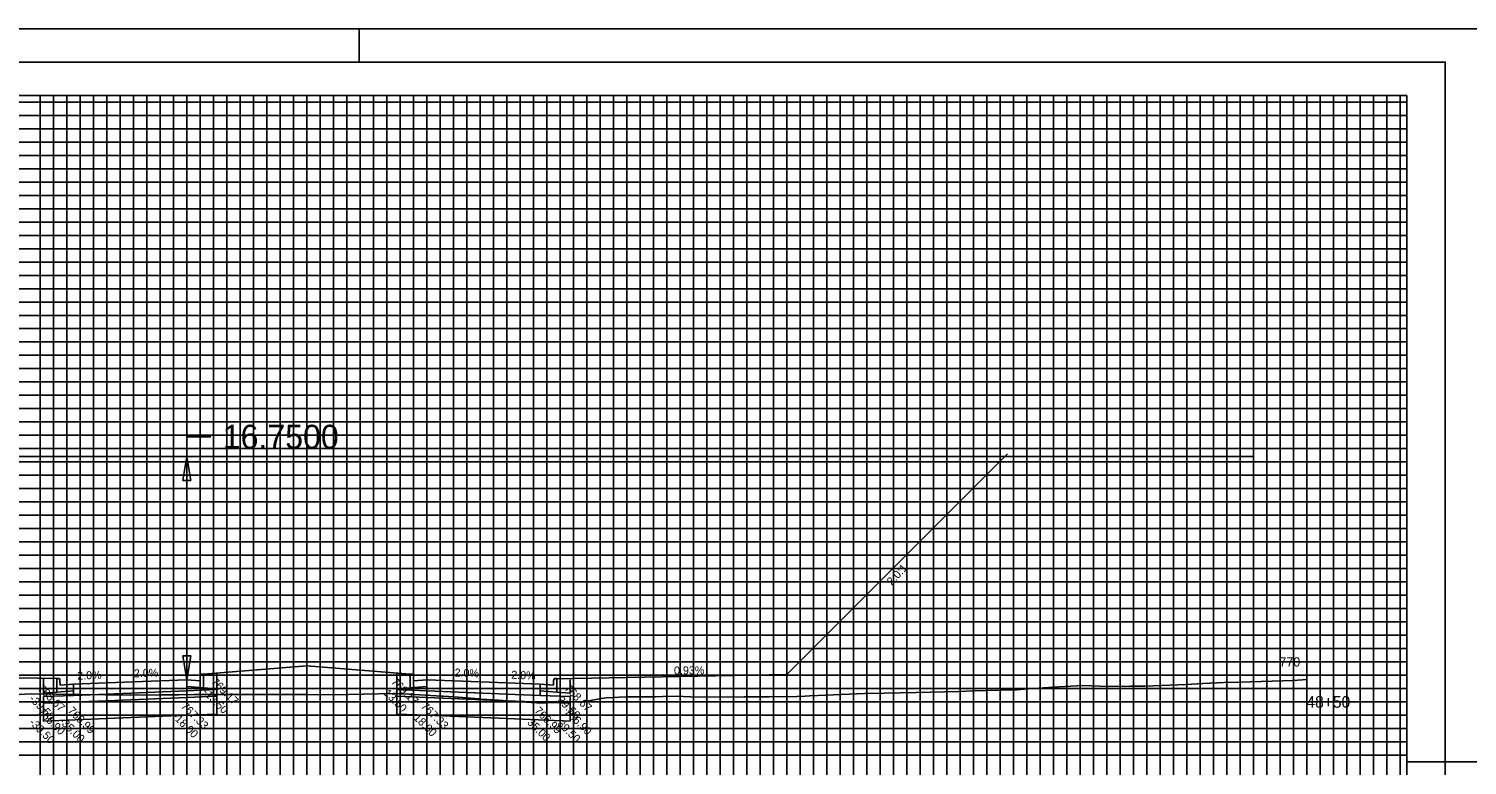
# Model space of a CAD drawing. Extents: x 578243 to 601557, y 174899 to 175559.
# Drawn here: x 600318.2 to 600533.9, y 175448.3 to 175558.8 of the extents above; entities that cross this region are included whole.
import ezdxf

# ---------------------------------------------------------------- set-up
doc = ezdxf.new("R2010")
doc.units = 0
for name, color, linetype in [('E_PROF_Grid', 7, 'Continuous'), ('E_PROF_GridMin', 7, 'Continuous'), ('P_CRDR_Label', 7, 'Continuous'), ('P_CRDR_Link', 7, 'Continuous'), ('P_E_XS_Ground', 7, 'Continuous'), ('P_RW_SlopeIntercepts', 7, 'Continuous'), ('P_XS_Text', 7, 'Continuous'), ('PLT_Sheet_Border', 7, 'Continuous'), ('PLT_Sheet_Info', 7, 'Continuous')]:
    doc.layers.add(name, color=color, linetype=linetype)

msp = doc.modelspace()

# ---------------------------------------------------------------- linework, layer by layer
at = {"layer": 'E_PROF_Grid'}
for p, q in [((600319.84, 175353.8), (600319.84, 175548.8)), ((600329.84, 175353.8), (600329.84, 175548.8)), ((600339.84, 175353.8), (600339.84, 175548.8)), ((600349.84, 175353.8), (600349.84, 175548.8)), ((600359.84, 175353.8), (600359.84, 175548.8)), ((600369.84, 175353.8), (600369.84, 175548.8)), ((600379.84, 175353.8), (600379.84, 175548.8)), ((600389.84, 175353.8), (600389.84, 175548.8)), ((600399.84, 175353.8), (600399.84, 175548.8)), ((600409.84, 175353.8), (600409.84, 175548.8)), ((600419.84, 175353.8), (600419.84, 175548.8)), ((600429.84, 175353.8), (600429.84, 175548.8)), ((600439.84, 175353.8), (600439.84, 175548.8)), ((600449.84, 175353.8), (600449.84, 175548.8)), ((600459.84, 175353.8), (600459.84, 175548.8)), ((600469.84, 175353.8), (600469.84, 175548.8)), ((600479.84, 175353.8), (600479.84, 175548.8)), ((600489.84, 175353.8), (600489.84, 175548.8)), ((600499.84, 175353.8), (600499.84, 175548.8)), ((600509.84, 175353.8), (600509.84, 175548.8)), ((600519.84, 175353.8), (600519.84, 175548.8)), ((600209.84, 175543.8), (600524.84, 175543.8)), ((600209.84, 175533.8), (600524.84, 175533.8)), ((600209.84, 175523.8), (600524.84, 175523.8)), ((600209.84, 175513.8), (600524.84, 175513.8)), ((600209.84, 175503.8), (600524.84, 175503.8)), ((600209.84, 175493.8), (600524.84, 175493.8)), ((600209.84, 175483.8), (600524.84, 175483.8)), ((600209.84, 175473.8), (600524.84, 175473.8)), ((600209.84, 175463.8), (600524.84, 175463.8)), ((600209.84, 175453.8), (600524.84, 175453.8))]:
    msp.add_line(p, q, dxfattribs=at)
at = {"layer": 'E_PROF_GridMin'}
for p, q in [((600321.84, 175353.8), (600321.84, 175548.8)), ((600323.84, 175353.8), (600323.84, 175548.8)), ((600325.84, 175353.8), (600325.84, 175548.8)), ((600327.84, 175353.8), (600327.84, 175548.8)), ((600331.84, 175353.8), (600331.84, 175548.8)), ((600333.84, 175353.8), (600333.84, 175548.8)), ((600335.84, 175353.8), (600335.84, 175548.8)), ((600337.84, 175353.8), (600337.84, 175548.8)), ((600341.84, 175353.8), (600341.84, 175548.8)), ((600343.84, 175353.8), (600343.84, 175548.8)), ((600345.84, 175353.8), (600345.84, 175548.8)), ((600347.84, 175353.8), (600347.84, 175548.8)), ((600351.84, 175353.8), (600351.84, 175548.8)), ((600353.84, 175353.8), (600353.84, 175548.8)), ((600355.84, 175353.8), (600355.84, 175548.8)), ((600357.84, 175353.8), (600357.84, 175548.8)), ((600361.84, 175353.8), (600361.84, 175548.8)), ((600363.84, 175353.8), (600363.84, 175548.8)), ((600365.84, 175353.8), (600365.84, 175548.8)), ((600367.84, 175353.8), (600367.84, 175548.8)), ((600371.84, 175353.8), (600371.84, 175548.8)), ((600373.84, 175353.8), (600373.84, 175548.8)), ((600375.84, 175353.8), (600375.84, 175548.8)), ((600377.84, 175353.8), (600377.84, 175548.8)), ((600381.84, 175353.8), (600381.84, 175548.8)), ((600383.84, 175353.8), (600383.84, 175548.8)), ((600385.84, 175353.8), (600385.84, 175548.8)), ((600387.84, 175353.8), (600387.84, 175548.8)), ((600391.84, 175353.8), (600391.84, 175548.8)), ((600393.84, 175353.8), (600393.84, 175548.8)), ((600395.84, 175353.8), (600395.84, 175548.8)), ((600397.84, 175353.8), (600397.84, 175548.8)), ((600401.84, 175353.8), (600401.84, 175548.8)), ((600403.84, 175353.8), (600403.84, 175548.8)), ((600405.84, 175353.8), (600405.84, 175548.8)), ((600407.84, 175353.8), (600407.84, 175548.8)), ((600411.84, 175353.8), (600411.84, 175548.8)), ((600413.84, 175353.8), (600413.84, 175548.8)), ((600415.84, 175353.8), (600415.84, 175548.8)), ((600417.84, 175353.8), (600417.84, 175548.8)), ((600421.84, 175353.8), (600421.84, 175548.8)), ((600423.84, 175353.8), (600423.84, 175548.8)), ((600425.84, 175353.8), (600425.84, 175548.8)), ((600427.84, 175353.8), (600427.84, 175548.8)), ((600431.84, 175353.8), (600431.84, 175548.8)), ((600433.84, 175353.8), (600433.84, 175548.8)), ((600435.84, 175353.8), (600435.84, 175548.8)), ((600437.84, 175353.8), (600437.84, 175548.8)), ((600441.84, 175353.8), (600441.84, 175548.8)), ((600443.84, 175353.8), (600443.84, 175548.8)), ((600445.84, 175353.8), (600445.84, 175548.8)), ((600447.84, 175353.8), (600447.84, 175548.8)), ((600451.84, 175353.8), (600451.84, 175548.8)), ((600453.84, 175353.8), (600453.84, 175548.8)), ((600455.84, 175353.8), (600455.84, 175548.8)), ((600457.84, 175353.8), (600457.84, 175548.8)), ((600461.84, 175353.8), (600461.84, 175548.8)), ((600463.84, 175353.8), (600463.84, 175548.8)), ((600465.84, 175353.8), (600465.84, 175548.8)), ((600467.84, 175353.8), (600467.84, 175548.8)), ((600471.84, 175353.8), (600471.84, 175548.8)), ((600473.84, 175353.8), (600473.84, 175548.8)), ((600475.84, 175353.8), (600475.84, 175548.8)), ((600477.84, 175353.8), (600477.84, 175548.8)), ((600481.84, 175353.8), (600481.84, 175548.8)), ((600483.84, 175353.8), (600483.84, 175548.8)), ((600485.84, 175353.8), (600485.84, 175548.8)), ((600487.84, 175353.8), (600487.84, 175548.8)), ((600491.84, 175353.8), (600491.84, 175548.8)), ((600493.84, 175353.8), (600493.84, 175548.8)), ((600495.84, 175353.8), (600495.84, 175548.8)), ((600497.84, 175353.8), (600497.84, 175548.8)), ((600501.84, 175353.8), (600501.84, 175548.8)), ((600503.84, 175353.8), (600503.84, 175548.8)), ((600505.84, 175353.8), (600505.84, 175548.8)), ((600507.84, 175353.8), (600507.84, 175548.8)), ((600511.84, 175353.8), (600511.84, 175548.8)), ((600513.84, 175353.8), (600513.84, 175548.8)), ((600515.84, 175353.8), (600515.84, 175548.8)), ((600517.84, 175353.8), (600517.84, 175548.8)), ((600521.84, 175353.8), (600521.84, 175548.8)), ((600523.84, 175353.8), (600523.84, 175548.8)), ((600209.84, 175547.8), (600524.84, 175547.8)), ((600209.84, 175545.8), (600524.84, 175545.8)), ((600209.84, 175541.8), (600524.84, 175541.8)), ((600209.84, 175539.8), (600524.84, 175539.8)), ((600209.84, 175537.8), (600524.84, 175537.8)), ((600209.84, 175535.8), (600524.84, 175535.8)), ((600209.84, 175531.8), (600524.84, 175531.8)), ((600209.84, 175529.8), (600524.84, 175529.8)), ((600209.84, 175527.8), (600524.84, 175527.8)), ((600209.84, 175525.8), (600524.84, 175525.8)), ((600209.84, 175521.8), (600524.84, 175521.8)), ((600209.84, 175519.8), (600524.84, 175519.8)), ((600209.84, 175517.8), (600524.84, 175517.8)), ((600209.84, 175515.8), (600524.84, 175515.8)), ((600209.84, 175511.8), (600524.84, 175511.8)), ((600209.84, 175509.8), (600524.84, 175509.8)), ((600209.84, 175507.8), (600524.84, 175507.8)), ((600209.84, 175505.8), (600524.84, 175505.8)), ((600209.84, 175501.8), (600524.84, 175501.8)), ((600209.84, 175499.8), (600524.84, 175499.8)), ((600209.84, 175497.8), (600524.84, 175497.8)), ((600209.84, 175495.8), (600524.84, 175495.8)), ((600209.84, 175491.8), (600524.84, 175491.8)), ((600209.84, 175489.8), (600524.84, 175489.8)), ((600209.84, 175487.8), (600524.84, 175487.8)), ((600209.84, 175485.8), (600524.84, 175485.8)), ((600209.84, 175481.8), (600524.84, 175481.8)), ((600209.84, 175479.8), (600524.84, 175479.8)), ((600209.84, 175477.8), (600524.84, 175477.8)), ((600209.84, 175475.8), (600524.84, 175475.8)), ((600209.84, 175471.8), (600524.84, 175471.8)), ((600209.84, 175469.8), (600524.84, 175469.8)), ((600209.84, 175467.8), (600524.84, 175467.8)), ((600209.84, 175465.8), (600524.84, 175465.8)), ((600209.84, 175461.8), (600524.84, 175461.8)), ((600209.84, 175459.8), (600524.84, 175459.8)), ((600209.84, 175457.8), (600524.84, 175457.8)), ((600209.84, 175455.8), (600524.84, 175455.8)), ((600209.84, 175451.8), (600524.84, 175451.8)), ((600209.84, 175449.8), (600524.84, 175449.8))]:
    msp.add_line(p, q, dxfattribs=at)
at = {"layer": 'P_CRDR_Link'}
msp.add_line((600464.95, 175495.04), (600431.84, 175461.93), dxfattribs=at)
for points in [[(600344.34, 175461.97), (600359.84, 175463.21)], [(600344.34, 175461.97), (600359.84, 175463.21)], [(600359.84, 175463.21), (600344.34, 175461.97)], [(600344.34, 175461.97), (600346.34, 175462.13)], [(600346.34, 175462.13), (600346.34, 175459.77)], [(600346.34, 175462.13), (600346.34, 175459.77)], [(600346.34, 175462.13), (600346.34, 175459.77)], [(600346.34, 175462.13), (600346.34, 175462.13)], [(600346.34, 175462.13), (600346.34, 175462.13)], [(600359.84, 175463.21), (600375.34, 175461.97)], [(600359.84, 175463.21), (600375.34, 175461.97)], [(600375.34, 175461.97), (600359.84, 175463.21)], [(600375.34, 175461.97), (600373.34, 175462.13)], [(600373.34, 175462.13), (600373.34, 175459.77)], [(600373.34, 175462.13), (600373.34, 175459.77)], [(600373.34, 175462.13), (600373.34, 175459.77)], [(600373.34, 175462.13), (600373.34, 175462.13)], [(600373.34, 175462.13), (600373.34, 175462.13)], [(600322.34, 175461.29), (600287.84, 175461.93)], [(600320.34, 175461.34), (600320.34, 175459.09)], [(600320.34, 175461.13), (600320.34, 175459.09)], [(600320.34, 175461.13), (600320.34, 175459.09)], [(600322.66, 175461.29), (600322.34, 175461.29)], [(600322.66, 175461.29), (600322.34, 175461.29)], [(600322.34, 175461.29), (600322.34, 175459.25)], [(600322.34, 175459.25), (600322.34, 175461.29)], [(600322.74, 175461.25), (600322.66, 175461.29)], [(600322.74, 175461.25), (600322.66, 175461.29)], [(600322.8, 175461.13), (600322.74, 175461.25)], [(600322.8, 175461.13), (600322.74, 175461.25)], [(600322.83, 175460.97), (600322.8, 175461.13)], [(600322.83, 175460.97), (600322.8, 175461.13)], [(600322.84, 175460.29), (600322.83, 175460.97)], [(600322.84, 175460.29), (600322.83, 175460.97)], [(600324.84, 175460.45), (600322.84, 175460.29)], [(600324.84, 175460.45), (600322.84, 175460.29)], [(600329.84, 175460.65), (600324.84, 175460.45)], [(600324.84, 175460.45), (600324.84, 175458.78)], [(600324.84, 175459.45), (600324.84, 175460.45)], [(600341.84, 175461.13), (600329.84, 175460.65)], [(600329.84, 175460.65), (600329.84, 175458.98)], [(600329.84, 175460.65), (600329.84, 175458.98)], [(600341.84, 175461.13), (600341.84, 175459.46)], [(600341.84, 175461.13), (600341.84, 175459.46)], [(600341.84, 175461.13), (600341.84, 175459.46)], [(600341.84, 175461.13), (600343.84, 175460.97)], [(600341.84, 175461.13), (600343.84, 175460.97)], [(600341.84, 175460.13), (600341.84, 175461.13)], [(600344.34, 175459.93), (600341.84, 175460.13)], [(600344.34, 175459.93), (600341.84, 175460.13)], [(600343.84, 175460.97), (600343.85, 175461.65)], [(600343.84, 175460.97), (600343.85, 175461.65)], [(600343.85, 175461.65), (600343.88, 175461.81)], [(600343.85, 175461.65), (600343.88, 175461.81)], [(600343.88, 175461.81), (600343.94, 175461.93)], [(600343.88, 175461.81), (600343.94, 175461.93)], [(600343.94, 175461.93), (600344.02, 175461.97)], [(600343.94, 175461.93), (600344.02, 175461.97)], [(600344.02, 175461.97), (600344.34, 175461.97)], [(600344.02, 175461.97), (600344.34, 175461.97)], [(600344.34, 175461.97), (600344.34, 175459.93)], [(600344.34, 175459.93), (600344.34, 175461.97)], [(600344.34, 175461.97), (600344.34, 175461.97)], [(600346.34, 175459.77), (600344.34, 175459.93)], [(600373.34, 175459.77), (600375.34, 175459.93)], [(600375.66, 175461.97), (600375.34, 175461.97)], [(600375.66, 175461.97), (600375.34, 175461.97)], [(600375.34, 175461.97), (600375.34, 175459.93)], [(600375.34, 175459.93), (600375.34, 175461.97)], [(600375.34, 175461.97), (600375.34, 175461.97)], [(600375.34, 175459.93), (600377.84, 175460.13)], [(600375.34, 175459.93), (600377.84, 175460.13)], [(600375.74, 175461.93), (600375.66, 175461.97)], [(600375.74, 175461.93), (600375.66, 175461.97)], [(600375.8, 175461.81), (600375.74, 175461.93)], [(600375.8, 175461.81), (600375.74, 175461.93)], [(600375.83, 175461.65), (600375.8, 175461.81)], [(600375.83, 175461.65), (600375.8, 175461.81)], [(600375.84, 175460.97), (600375.83, 175461.65)], [(600375.84, 175460.97), (600375.83, 175461.65)], [(600377.84, 175461.13), (600375.84, 175460.97)], [(600377.84, 175461.13), (600375.84, 175460.97)], [(600377.84, 175461.13), (600389.84, 175460.65)], [(600377.84, 175461.13), (600377.84, 175459.46)], [(600377.84, 175461.13), (600377.84, 175459.46)], [(600377.84, 175461.13), (600377.84, 175459.46)], [(600377.84, 175460.13), (600377.84, 175461.13)], [(600389.84, 175460.65), (600389.84, 175458.98)], [(600389.84, 175460.65), (600394.84, 175460.45)], [(600389.84, 175460.65), (600389.84, 175458.98)], [(600394.84, 175460.45), (600394.84, 175458.78)], [(600394.84, 175460.45), (600396.84, 175460.29)], [(600394.84, 175460.45), (600396.84, 175460.29)], [(600394.84, 175459.45), (600394.84, 175460.45)], [(600396.84, 175460.29), (600396.85, 175460.97)], [(600396.84, 175460.29), (600396.85, 175460.97)], [(600396.85, 175460.97), (600396.88, 175461.13)], [(600396.85, 175460.97), (600396.88, 175461.13)], [(600396.88, 175461.13), (600396.94, 175461.25)], [(600396.88, 175461.13), (600396.94, 175461.25)], [(600396.94, 175461.25), (600397.02, 175461.29)], [(600396.94, 175461.25), (600397.02, 175461.29)], [(600397.02, 175461.29), (600397.34, 175461.29)], [(600397.02, 175461.29), (600397.34, 175461.29)], [(600397.18, 175461.28), (600431.84, 175461.93)], [(600397.34, 175461.29), (600397.34, 175459.25)], [(600397.34, 175459.25), (600397.34, 175461.29)], [(600399.34, 175461.13), (600399.34, 175459.09)], [(600399.34, 175461.13), (600399.34, 175459.09)], [(600399.34, 175461.13), (600399.34, 175459.09)], [(600320.34, 175459.09), (600322.34, 175459.25)], [(600324.84, 175458.78), (600320.34, 175458.6)], [(600320.34, 175458.6), (600320.34, 175457.6)], [(600329.84, 175457.98), (600320.34, 175457.6)], [(600322.34, 175459.25), (600324.84, 175459.45)], [(600322.34, 175459.25), (600324.84, 175459.45)], [(600329.84, 175458.98), (600324.84, 175458.78)], [(600341.84, 175459.46), (600329.84, 175458.98)], [(600329.84, 175458.98), (600329.84, 175457.98)], [(600329.84, 175458.98), (600329.84, 175457.98)], [(600341.84, 175458.46), (600329.84, 175457.98)], [(600329.84, 175457.98), (600329.84, 175455.31)], [(600329.84, 175457.98), (600329.84, 175455.31)], [(600346.34, 175459.64), (600341.84, 175459.46)], [(600341.84, 175459.46), (600341.84, 175458.46)], [(600341.84, 175459.46), (600341.84, 175458.46)], [(600341.84, 175459.46), (600341.84, 175458.46)], [(600346.34, 175458.64), (600341.84, 175458.46)], [(600341.84, 175458.46), (600341.84, 175455.79)], [(600341.84, 175458.46), (600341.84, 175455.79)], [(600341.84, 175458.46), (600341.84, 175455.79)], [(600346.34, 175459.64), (600346.34, 175458.64)], [(600346.34, 175458.64), (600346.34, 175455.97)], [(600373.34, 175459.64), (600377.84, 175459.46)], [(600373.34, 175459.64), (600373.34, 175458.64)], [(600373.34, 175458.64), (600377.84, 175458.46)], [(600373.34, 175458.64), (600373.34, 175455.97)], [(600377.84, 175459.46), (600389.84, 175458.98)], [(600377.84, 175459.46), (600377.84, 175458.46)], [(600377.84, 175459.46), (600377.84, 175458.46)], [(600377.84, 175459.46), (600377.84, 175458.46)], [(600377.84, 175458.46), (600389.84, 175457.98)], [(600377.84, 175458.46), (600377.84, 175455.79)], [(600377.84, 175458.46), (600377.84, 175455.79)], [(600377.84, 175458.46), (600377.84, 175455.79)], [(600389.84, 175458.98), (600389.84, 175457.98)], [(600389.84, 175458.98), (600394.84, 175458.78)], [(600389.84, 175458.98), (600389.84, 175457.98)], [(600389.84, 175457.98), (600389.84, 175455.31)], [(600389.84, 175457.98), (600399.34, 175457.6)], [(600389.84, 175457.98), (600389.84, 175455.31)], [(600397.34, 175459.25), (600394.84, 175459.45)], [(600397.34, 175459.25), (600394.84, 175459.45)], [(600394.84, 175458.78), (600399.34, 175458.6)], [(600399.34, 175459.09), (600397.34, 175459.25)], [(600399.34, 175458.6), (600399.34, 175457.6)], [(600320.34, 175457.6), (600320.34, 175454.93)], [(600341.84, 175455.79), (600329.84, 175455.31)], [(600341.84, 175455.79), (600346.34, 175455.97)], [(600377.84, 175455.79), (600373.34, 175455.97)], [(600377.84, 175455.79), (600389.84, 175455.31)], [(600399.34, 175457.6), (600399.34, 175454.93)], [(600329.84, 175455.31), (600320.34, 175454.93)], [(600389.84, 175455.31), (600399.34, 175454.93)]]:
    msp.add_lwpolyline(points, dxfattribs=at)
at = {"layer": 'P_E_XS_Ground'}
msp.add_lwpolyline([(600313.38, 175458.77), (600318.6, 175459), (600333.38, 175458.83), (600337.75, 175458.84), (600340.65, 175458.85), (600342.96, 175458.93), (600358.31, 175458.9), (600359.84, 175458.89), (600363.88, 175458.88), (600372.81, 175459.06), (600373.16, 175459.07), (600373.33, 175459.06), (600373.46, 175459.05), (600373.68, 175459.03), (600374.4, 175459.01), (600380.06, 175458.68), (600380.36, 175458.64), (600382.54, 175458.49), (600385.7, 175458.24), (600385.86, 175458.23), (600387.84, 175458.11), (600389.94, 175457.97), (600393.49, 175457.69), (600394.37, 175457.64), (600394.65, 175457.62), (600395.64, 175457.65), (600401.25, 175457.8), (600404.07, 175458.33), (600404.74, 175458.43), (600407.69, 175458.55), (600412.14, 175458.58), (600413.25, 175458.63), (600415.27, 175458.68), (600417.39, 175458.57), (600424.34, 175458.52), (600425.45, 175458.55), (600429.27, 175458.56), (600433.36, 175458.59), (600434.6, 175458.66), (600435.28, 175458.69), (600443.56, 175459.05), (600446.42, 175459.1), (600451.23, 175459.19), (600457.66, 175459.37), (600459.69, 175459.44), (600461.66, 175459.49), (600466.36, 175459.63), (600468.03, 175459.77), (600472.64, 175460.05), (600476.23, 175460.24), (600480.08, 175460.11), (600483.34, 175460.16), (600485.55, 175460.16), (600491.79, 175460.41), (600494.24, 175460.56), (600497.44, 175460.7), (600499.8, 175460.75), (600507.86, 175461), (600509.84, 175461.16)], dxfattribs=at)
at = {"layer": 'P_RW_SlopeIntercepts'}
for p, q in [((600341.84, 175497.55), (600345.44, 175497.55)), ((600341.84, 175461.13), (600341.84, 175497.55)), ((600241.84, 175494.63), (600501.84, 175494.63))]:
    msp.add_line(p, q, dxfattribs=at)
for points in [[(600341.24, 175491.03), (600342.44, 175491.03), (600341.84, 175494.63)], [(600341.24, 175464.73), (600342.44, 175464.73), (600341.84, 175461.13)]]:
    msp.add_lwpolyline(points, close=True, dxfattribs=at)
at = {"layer": 'PLT_Sheet_Border'}
for points in [[(600197.19, 175338.8), (600537.19, 175338.8), (600537.19, 175558.8), (600197.19, 175558.8)], [(600199.59, 175343.8), (600530.59, 175343.8), (600530.59, 175553.8), (600199.59, 175553.8)]]:
    msp.add_lwpolyline(points, close=True, dxfattribs=at)
at = {"layer": 'PLT_Sheet_Info'}
for p, q in [((600362.69, 175558.8), (600372.69, 175558.8)), ((600367.69, 175558.8), (600367.69, 175553.8)), ((600527.19, 175558.8), (600537.19, 175558.8)), ((600209.84, 175548.8), (600524.84, 175548.8)), ((600524.84, 175348.8), (600524.84, 175548.8)), ((600537.19, 175448.8), (600524.84, 175448.8))]:
    msp.add_line(p, q, dxfattribs=at)

# ---------------------------------------------------------------- texts
at = {"layer": 'P_CRDR_Label'}
for s, rotation, p in [('2.0:1', 46.711, (600447.58, 175475.21)), ('2.0%', 2.2906, (600325.44, 175461.13)), ('2.0%', 2.2906, (600333.94, 175461.47)), ('2.0%', 357.7094, (600381.99, 175461.62)), ('2.0%', 357.7094, (600390.49, 175461.28)), ('0.93%', 0.4313, (600414.93, 175461.92)), ('768.67', 315, (600319.41, 175459.71)), ('769.17', 315, (600345.41, 175460.71)), ('769.17', 315, (600372.41, 175460.71)), ('768.67', 315, (600398.41, 175459.71)), ('-39.50', 315, (600318.13, 175458.15)), ('767.33', 315, (600340.91, 175457.05)), ('767.33', 315, (600340.91, 175457.05)), ('767.33', 315, (600340.91, 175457.05)), ('-13.50', 315, (600344.13, 175459.15)), ('13.50', 315, (600371.3, 175458.99)), ('767.33', 315, (600376.91, 175457.05)), ('767.33', 315, (600376.91, 175457.05)), ('767.33', 315, (600376.91, 175457.05)), ('39.50', 315, (600397.32, 175457.96)), ('766.90', 315, (600319.41, 175456.19)), ('766.99', 315, (600323.91, 175456.37)), ('-18.00', 315, (600339.62, 175455.5)), ('-18.00', 315, (600339.62, 175455.5)), ('-18.00', 315, (600339.62, 175455.5)), ('18.00', 315, (600375.78, 175455.33)), ('18.00', 315, (600375.78, 175455.33)), ('18.00', 315, (600375.78, 175455.33)), ('766.99', 315, (600393.91, 175456.37)), ('766.90', 315, (600398.41, 175456.19)), ('-39.50', 315, (600318.14, 175454.62)), ('-35.00', 315, (600322.62, 175454.81)), ('35.00', 315, (600392.82, 175454.62)), ('39.50', 315, (600397.33, 175454.43))]:
    msp.add_text(s, height=1.2, rotation=rotation, dxfattribs=at).set_placement(p)
at = {"layer": 'P_RW_SlopeIntercepts'}
msp.add_text('16.7500', height=3.6, dxfattribs=at).set_placement((600347.24, 175495.78))
at = {"layer": 'P_XS_Text'}
for s, height, p in [('770', 1.4, (600505.72, 175463.1)), ('48+50', 1.75, (600509.77, 175456.93))]:
    msp.add_text(s, height=height, rotation=360, dxfattribs=at).set_placement(p)

doc.saveas('drawing.dxf')
